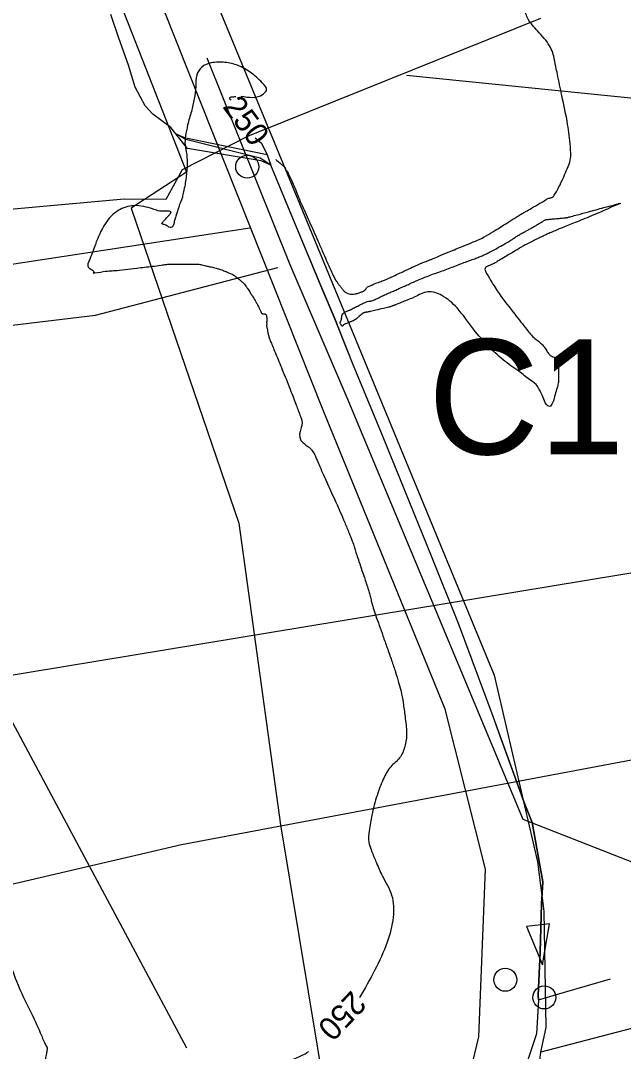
# Model space of a CAD drawing. Extents: x -478232 to -472707, y -1118753 to -1113967.
# Drawn here: x -475969.3 to -475864.4, y -1117320.7 to -1117141.4 of the extents above; entities that cross this region are included whole.
import ezdxf

# ---------------------------------------------------------------- set-up
doc = ezdxf.new("R2010")
doc.units = 0
for name, color, linetype in [('cesty', 7, 'Continuous'), ('el vedeni _VN', 7, 'Continuous'), ('el vedeni_NN', 7, 'Continuous'), ('el vedeni_VVN', 7, 'Continuous'), ('ObPÚ', 7, 'Continuous'), ('plyn_vtl', 7, 'Continuous'), ('silnice', 7, 'Continuous'), ('telekomunikační kabel_O2', 7, 'Continuous'), ('VAK_vodovod', 7, 'Continuous'), ('VAK_vodovod_přípojky', 7, 'Continuous'), ('Vrstevnice_hlavni', 7, 'Continuous'), ('Vrstevnice_popis', 7, 'Continuous')]:
    doc.layers.add(name, color=color, linetype=linetype)

msp = doc.modelspace()

# ---------------------------------------------------------------- linework, layer by layer
at = {"layer": 'cesty'}
msp.add_line((-475877.248, -1117298.53), (-475881.224, -1117298.963), dxfattribs=at)
msp.add_lwpolyline([(-475881.224, -1117298.963), (-475878.485, -1117305.652), (-475877.248, -1117298.53)], dxfattribs=at)
for centre in [(-475929.862, -1117166.808), (-475884.935, -1117308.251), (-475878.155, -1117311.325)]:
    msp.add_circle(centre, 2, dxfattribs=at)
at = {"layer": 'el vedeni _VN'}
msp.add_lwpolyline([(-476054.13, -1117068.87), (-476016.19, -1117179.43), (-476005.061, -1117199.42), (-475940.421, -1117320.088)], dxfattribs=at)
at = {"layer": 'el vedeni_NN'}
for points in [[(-475936.884, -1117147.842), (-475922.455, -1117183.822), (-475912.509, -1117206.959)], [(-476142.527, -1117233.564), (-476143.465, -1117231.005), (-476140.291, -1117228.14), (-476109.493, -1117209.467), (-476071.248, -1117205.717), (-476032.928, -1117201.185), (-475993.047, -1117197.048), (-475956.253, -1117192.65), (-475924.554, -1117184.37)], [(-475912.509, -1117206.959), (-475881.908, -1117280.308), (-475845.463, -1117294.572), (-475796.905, -1117294.234), (-475790.107, -1117303.085)]]:
    msp.add_lwpolyline(points, dxfattribs=at)
at = {"layer": 'el vedeni_VVN'}
for points in [[(-475278.421, -1117142.471), (-475502.649, -1117177.682), (-475743.53, -1117217.796), (-475998.47, -1117259.845), (-476243.025, -1117301.163), (-476469.01, -1117542.153)], [(-476280.708, -1117409.299), (-476225.714, -1117351.077), (-475941.309, -1117284.746), (-475941.309, -1117284.746), (-475650.164, -1117229.984), (-475650.164, -1117229.984), (-475374.719, -1117181.713), (-475324.354, -1117172.684)], [(-476280.708, -1117409.299), (-476225.714, -1117351.077), (-475941.309, -1117284.746), (-475941.309, -1117284.746), (-475650.164, -1117229.984), (-475650.164, -1117229.984), (-475374.719, -1117181.713), (-475324.354, -1117172.684)]]:
    msp.add_lwpolyline(points, dxfattribs=at)
at = {"layer": 'ObPÚ'}
msp.add_lwpolyline([(-475878.82, -1117141.03), (-475927.98, -1117160.79), (-475929.84, -1117161.54), (-475941.17, -1117167.34), (-475944.04, -1117172.5), (-475951.31, -1117172.43), (-476004.5, -1117177.28), (-476018.94, -1117179.19), (-476061.7, -1117183.99), (-476084.27, -1117186.17), (-476089.54, -1117186.61), (-476093.95, -1117187.01), (-476104.79, -1117188.01), (-476125.75, -1117189.99), (-476140.43, -1117190.84), (-476150.96, -1117191.92), (-476159.5, -1117192.77), (-476224.13, -1117203.13), (-476225.41, -1117191.08), (-476226.67, -1117162.34), (-476231.32, -1117146.23), (-476236.27, -1117130.89)], dxfattribs=at)
at = {"layer": 'plyn_vtl'}
msp.add_lwpolyline([(-475595.138, -1117298.191), (-475598.3, -1117295.92), (-475667.47, -1117237.33), (-475686.33, -1117221.12), (-475738.19, -1117171.6), (-475740.56, -1117170), (-475797.11, -1117162.8), (-475845.33, -1117156.66), (-475902.14, -1117150.95)], dxfattribs=at)
at = {"layer": 'silnice'}
for points in [[(-475903.982, -1117378.322), (-475889.519, -1117318.176), (-475888.389, -1117289.008), (-475895.395, -1117261.196), (-475916.638, -1117209.19), (-475969.886, -1117075.455), (-476021.05, -1116948.737), (-476052.923, -1116863.979), (-476081.44, -1116727.192), (-476114.99, -1116491.378), (-476128.411, -1116405.781), (-476137.637, -1116368.017), (-476162.8, -1116322.7), (-476200.543, -1116268.153), (-476239.965, -1116179.199), (-476260.934, -1116109.546), (-476288.613, -1116007.164), (-476289.451, -1115970.24), (-476274.354, -1115930.798), (-476261.922, -1115907.288), (-476366.595, -1115823.727)], [(-476424.073, -1117228.817), (-476282.324, -1117220.425), (-476211.029, -1117212.034), (-476121.67, -1117200.902), (-476029.858, -1117192.732), (-475929.409, -1117177.447)]]:
    msp.add_lwpolyline(points, dxfattribs=at)
at = {"layer": 'telekomunikační kabel_O2'}
for points in [[(-475967.4, -1117098.97), (-475940.43, -1117167.78), (-475950.06, -1117174), (-475931.33, -1117228.82), (-475924.1, -1117281.32), (-475911.23, -1117358.65), (-475927.92, -1117430.83), (-475926.17, -1117443.9), (-475937.75, -1117500.32), (-475940.1, -1117518.94), (-475929.72, -1117521.06), (-475934.27, -1117556.02), (-475935.89, -1117566.02), (-475936.969, -1117573.032)], [(-475950.5, -1117149.33), (-475952.3, -1117144.28), (-475953.59, -1117140.32)], [(-475942.29, -1117161.11), (-475943.19, -1117159.98), (-475946.28, -1117157.66), (-475947.65, -1117156.22), (-475949.35, -1117152.98), (-475950.35, -1117149.74), (-475950.5, -1117149.33)], [(-475925.77, -1117166.55), (-475927.6, -1117165.32), (-475940.53, -1117162.1), (-475942.29, -1117161.11)], [(-475925.77, -1117166.55), (-475927.41, -1117165.77), (-475940.26, -1117163.67), (-475942.29, -1117161.11)], [(-475941.28, -1117161.55), (-475942.29, -1117161.11)], [(-475926.38, -1117164.74), (-475940.58, -1117161.86), (-475941.28, -1117161.55)], [(-475928.5, -1117161.78), (-475927.37, -1117162.72), (-475926.38, -1117164.74)], [(-475926.38, -1117164.74), (-475925.77, -1117166.55)], [(-475912.112, -1117199.556), (-475914.73, -1117193.01), (-475916.77, -1117188.24), (-475925.77, -1117166.55)], [(-475923.355, -1117172.37), (-475916.77, -1117188.24), (-475914.73, -1117193.01), (-475911.57, -1117200.91), (-475906.35, -1117213.5), (-475897.84, -1117234.5), (-475893.13, -1117246.24), (-475887.26, -1117261.95), (-475881.63, -1117277.42), (-475880.27, -1117280.87), (-475878.41, -1117291.19), (-475878.66, -1117295.04), (-475878.84, -1117303.44), (-475879.2, -1117310.91), (-475879.17, -1117311.76)], [(-475879.17, -1117311.76), (-475879.2, -1117310.91), (-475878.84, -1117303.44), (-475878.66, -1117295.04), (-475878.41, -1117291.19), (-475880.27, -1117280.87), (-475881.63, -1117277.42), (-475886.596, -1117263.775)], [(-475879.17, -1117311.76), (-475874.62, -1117310.39), (-475866.596, -1117308.086)], [(-475879.17, -1117311.76), (-475879.52, -1117317.65), (-475882.94, -1117327.87), (-475883.65, -1117331.16), (-475885.38, -1117336.41), (-475888.04, -1117344.37), (-475889.45, -1117349.71), (-475891.45, -1117356.54)]]:
    msp.add_lwpolyline(points, dxfattribs=at)
at = {"layer": 'VAK_vodovod'}
msp.add_lwpolyline([(-475961.022, -1117076.006), (-475947.88, -1117107.78), (-475947.26, -1117108.989), (-475886.863, -1117255.251), (-475879.338, -1117287.714), (-475878.218, -1117296.341), (-475877.862, -1117316.562), (-475878.829, -1117320.819), (-475879.236, -1117324.31), (-475879.403, -1117324.54), (-475921.268, -1117487.378), (-475934.347, -1117574.649), (-475937.667, -1117596.666), (-475938.465, -1117600.746), (-475938.582, -1117601.233), (-475938.757, -1117601.897), (-475940.979, -1117601.583)], dxfattribs=at)
at = {"layer": 'VAK_vodovod_přípojky'}
msp.add_lwpolyline([(-475878.829, -1117320.819), (-475878.667, -1117320.807), (-475780.172, -1117295.12), (-475777.144, -1117294.881), (-475772.889, -1117306.106), (-475760.456, -1117318.245), (-475730.382, -1117337.683), (-475709.998, -1117331.986)], dxfattribs=at)
at = {"layer": 'Vrstevnice_hlavni'}
for points in [[(-475924.869, -1117165.582), (-475924.177, -1117166.164), (-475923.893, -1117166.407), (-475923.671, -1117166.602), (-475923.511, -1117166.749), (-475923.274, -1117167.084), (-475922.96, -1117167.608), (-475922.569, -1117168.319), (-475922.125, -1117169.249), (-475921.627, -1117170.396), (-475921.076, -1117171.761), (-475920.466, -1117173.201), (-475919.798, -1117174.717), (-475919.072, -1117176.307), (-475918.325, -1117177.977), (-475917.556, -1117179.725), (-475916.766, -1117181.553), (-475916.094, -1117183.094), (-475915.54, -1117184.347), (-475915.104, -1117185.312), (-475914.712, -1117186.097), (-475914.365, -1117186.7), (-475914.063, -1117187.123), (-475913.735, -1117187.557), (-475913.38, -1117188.002), (-475913, -1117188.458), (-475912.579, -1117188.775), (-475912.117, -1117188.951), (-475911.613, -1117188.986), (-475911.088, -1117188.941), (-475910.541, -1117188.813), (-475909.972, -1117188.605), (-475909.544, -1117188.384), (-475909.257, -1117188.152), (-475909.111, -1117187.908), (-475908.646, -1117187.607), (-475907.862, -1117187.25), (-475906.759, -1117186.836), (-475905.955, -1117186.527), (-475905.45, -1117186.324), (-475905.244, -1117186.226), (-475904.511, -1117185.883), (-475903.25, -1117185.295), (-475901.462, -1117184.461), (-475900.145, -1117183.861), (-475899.299, -1117183.496), (-475898.924, -1117183.367), (-475898.518, -1117183.211), (-475898.08, -1117183.03), (-475897.611, -1117182.823), (-475896.487, -1117182.352), (-475894.709, -1117181.617), (-475892.277, -1117180.618), (-475890.544, -1117179.904), (-475889.51, -1117179.475), (-475889.176, -1117179.331), (-475888.258, -1117178.808), (-475886.758, -1117177.905), (-475884.675, -1117176.622), (-475883.241, -1117175.734), (-475882.454, -1117175.242), (-475882.317, -1117175.146), (-475882.189, -1117175.064), (-475882.073, -1117174.997), (-475881.967, -1117174.944), (-475881.403, -1117174.622), (-475880.381, -1117174.03), (-475878.901, -1117173.169), (-475877.91, -1117172.594), (-475877.408, -1117172.306), (-475877.395, -1117172.303), (-475877.37, -1117172.3), (-475877.333, -1117172.298), (-475877.284, -1117172.296), (-475877.172, -1117172.269), (-475876.996, -1117172.219), (-475876.756, -1117172.145), (-475876.422, -1117171.763), (-475875.994, -1117171.074), (-475875.471, -1117170.078), (-475874.914, -1117168.901), (-475874.321, -1117167.542), (-475873.694, -1117166.003), (-475873.615, -1117163.305), (-475874.083, -1117159.45), (-475875.099, -1117154.435), (-475875.869, -1117150.689), (-475876.392, -1117148.211), (-475876.669, -1117147.001), (-475877.255, -1117145.76), (-475878.15, -1117144.488), (-475879.354, -1117143.187), (-475880.245, -1117142.157), (-475880.821, -1117141.4), (-475881.084, -1117140.914), (-475881.418, -1117139.944), (-475881.822, -1117138.488)], [(-475930.918, -1117154.529), (-475927.091, -1117154.196), (-475926.503, -1117153.48), (-475927.24, -1117152.214), (-475929.302, -1117150.397), (-475931.471, -1117149.215), (-475933.748, -1117148.667), (-475936.132, -1117148.753), (-475937.769, -1117149.482), (-475938.66, -1117150.856), (-475938.804, -1117152.873), (-475939.115, -1117154.995), (-475939.594, -1117157.22), (-475940.24, -1117159.55), (-475940.601, -1117161.482), (-475940.678, -1117163.016), (-475940.47, -1117164.152), (-475940.352, -1117165.284), (-475940.323, -1117166.413), (-475940.383, -1117167.539), (-475940.507, -1117168.708), (-475940.696, -1117169.92), (-475940.948, -1117171.176), (-475941.162, -1117172.102), (-475941.336, -1117172.697), (-475941.472, -1117172.962), (-475941.64, -1117173.385), (-475941.84, -1117173.966), (-475942.072, -1117174.704), (-475942.295, -1117175.442), (-475942.51, -1117176.178), (-475942.715, -1117176.914), (-475942.981, -1117177.326), (-475943.307, -1117177.413), (-475943.694, -1117177.176), (-475944.026, -1117176.997), (-475944.304, -1117176.874), (-475944.528, -1117176.808), (-475944.67, -1117176.742), (-475944.729, -1117176.675), (-475944.706, -1117176.609), (-475944.521, -1117176.383), (-475944.174, -1117175.997), (-475943.665, -1117175.452), (-475943.322, -1117175.07), (-475943.144, -1117174.851), (-475943.131, -1117174.794), (-475944.198, -1117174.565), (-475946.345, -1117174.163), (-475949.572, -1117173.588), (-475952.308, -1117174.424), (-475954.553, -1117176.67), (-475956.307, -1117180.326), (-475957.293, -1117182.884), (-475957.511, -1117184.344), (-475956.96, -1117184.706), (-475956.631, -1117184.974), (-475956.523, -1117185.148), (-475956.636, -1117185.228), (-475955.435, -1117185.138), (-475952.922, -1117184.878), (-475949.095, -1117184.447), (-475946.401, -1117184.135), (-475944.839, -1117183.942), (-475944.409, -1117183.867), (-475944.026, -1117183.817), (-475943.69, -1117183.791), (-475943.401, -1117183.789), (-475942.688, -1117183.78), (-475941.551, -1117183.761), (-475939.989, -1117183.735), (-475938.839, -1117183.747), (-475938.1, -1117183.797), (-475937.772, -1117183.886), (-475937.265, -1117184.007), (-475936.577, -1117184.16), (-475935.71, -1117184.344), (-475934.887, -1117184.569), (-475934.109, -1117184.835), (-475933.375, -1117185.14), (-475932.838, -1117185.366), (-475932.498, -1117185.513), (-475932.355, -1117185.581), (-475932.074, -1117185.779), (-475931.655, -1117186.106), (-475931.097, -1117186.562), (-475930.689, -1117186.908), (-475930.429, -1117187.143), (-475930.318, -1117187.267), (-475930.097, -1117187.576), (-475929.766, -1117188.071), (-475929.325, -1117188.751), (-475928.979, -1117189.287), (-475928.728, -1117189.677), (-475928.572, -1117189.922), (-475928.361, -1117190.294), (-475928.094, -1117190.794)], [(-475932.653, -1117155.22), (-475932.923, -1117154.883), (-475932.876, -1117154.759), (-475932.647, -1117154.679), (-475931.823, -1117154.607)], [(-475900.706, -1117186.785), (-475899.805, -1117186.392), (-475898.808, -1117185.988), (-475897.717, -1117185.575), (-475896.532, -1117185.153), (-475895.378, -1117184.731), (-475894.256, -1117184.308), (-475893.166, -1117183.885), (-475892.136, -1117183.495), (-475891.165, -1117183.136), (-475890.254, -1117182.81), (-475889.46, -1117182.504), (-475888.782, -1117182.22), (-475888.221, -1117181.958), (-475887.479, -1117181.575), (-475886.556, -1117181.073), (-475885.451, -1117180.451), (-475884.521, -1117179.91), (-475883.768, -1117179.45), (-475883.19, -1117179.071), (-475882.583, -1117178.7), (-475881.946, -1117178.336), (-475881.28, -1117177.98), (-475880.766, -1117177.703), (-475880.403, -1117177.507), (-475880.193, -1117177.39), (-475879.832, -1117177.175), (-475879.321, -1117176.862), (-475878.659, -1117176.449), (-475878.199, -1117176.17), (-475877.94, -1117176.025), (-475877.882, -1117176.013), (-475877.499, -1117175.973), (-475876.792, -1117175.905), (-475875.76, -1117175.809), (-475875.003, -1117175.737), (-475874.521, -1117175.688), (-475874.314, -1117175.663), (-475874.071, -1117175.617), (-475873.793, -1117175.551), (-475873.478, -1117175.465), (-475872.371, -1117175.165), (-475870.469, -1117174.652), (-475867.775, -1117173.924), (-475865.95, -1117173.435), (-475864.996, -1117173.184), (-475864.912, -1117173.172), (-475865.491, -1117173.438), (-475866.735, -1117173.982), (-475868.643, -1117174.805), (-475870.335, -1117175.522), (-475871.814, -1117176.133), (-475873.078, -1117176.639), (-475874.242, -1117177.11), (-475875.308, -1117177.545), (-475876.274, -1117177.946), (-475877.165, -1117178.329), (-475877.982, -1117178.695), (-475878.725, -1117179.044), (-475879.521, -1117179.431), (-475880.372, -1117179.858), (-475881.277, -1117180.323), (-475881.999, -1117180.711), (-475882.54, -1117181.02), (-475882.898, -1117181.252), (-475883.522, -1117181.635), (-475884.411, -1117182.169), (-475885.565, -1117182.855), (-475886.364, -1117183.326), (-475886.808, -1117183.582), (-475886.896, -1117183.624), (-475887.19, -1117183.764), (-475887.691, -1117184.002), (-475888.399, -1117184.338), (-475887.946, -1117185.807), (-475886.332, -1117188.408), (-475883.558, -1117192.141), (-475881.439, -1117194.845), (-475879.975, -1117196.521), (-475879.166, -1117197.167), (-475878.487, -1117197.821), (-475877.938, -1117198.482), (-475877.52, -1117199.151), (-475877.096, -1117199.613), (-475876.667, -1117199.869), (-475875.8, -1117199.969)], [(-475875.8, -1117199.969), (-475875.68, -1117202.403), (-475875.658, -1117203.359), (-475875.673, -1117204.054), (-475875.726, -1117204.488), (-475875.922, -1117205.276), (-475876.259, -1117206.418), (-475876.739, -1117207.915), (-475877.248, -1117208.499), (-475877.786, -1117208.171), (-475878.353, -1117206.931), (-475878.805, -1117205.979), (-475879.141, -1117205.316), (-475879.361, -1117204.941), (-475880.402, -1117204.046), (-475882.264, -1117202.632), (-475884.948, -1117200.698), (-475887.689, -1117198.176), (-475890.488, -1117195.066), (-475893.345, -1117191.367), (-475895.998, -1117189.203), (-475898.449, -1117188.572), (-475900.697, -1117189.475), (-475902.312, -1117190.127), (-475903.293, -1117190.526), (-475903.642, -1117190.674), (-475903.924, -1117190.79), (-475904.137, -1117190.873), (-475904.284, -1117190.925), (-475904.422, -1117190.977), (-475904.554, -1117191.031), (-475904.678, -1117191.085), (-475905.203, -1117191.224), (-475906.13, -1117191.449), (-475907.459, -1117191.76), (-475908.393, -1117191.972), (-475908.932, -1117192.087), (-475909.077, -1117192.105), (-475909.225, -1117192.131), (-475909.377, -1117192.167), (-475909.532, -1117192.212), (-475909.671, -1117192.27), (-475909.793, -1117192.34), (-475909.9, -1117192.424), (-475910.088, -1117192.585), (-475910.358, -1117192.824), (-475910.71, -1117193.139), (-475911.018, -1117193.381), (-475911.281, -1117193.547), (-475911.499, -1117193.639), (-475911.684, -1117193.715), (-475911.836, -1117193.776), (-475911.953, -1117193.823), (-475912.145, -1117193.899), (-475912.41, -1117194.007), (-475912.749, -1117194.146), (-475912.996, -1117194.272), (-475913.15, -1117194.387), (-475913.212, -1117194.49), (-475913.28, -1117194.535), (-475913.355, -1117194.521), (-475913.436, -1117194.45), (-475913.514, -1117194.346), (-475913.588, -1117194.21), (-475913.659, -1117194.043), (-475913.681, -1117193.9), (-475913.654, -1117193.781), (-475913.58, -1117193.687), (-475913.508, -1117193.483), (-475913.439, -1117193.17), (-475913.374, -1117192.747), (-475913.218, -1117192.413), (-475912.972, -1117192.166), (-475912.636, -1117192.007), (-475912.366, -1117191.886), (-475912.161, -1117191.802), (-475912.023, -1117191.756), (-475911.881, -1117191.697), (-475911.735, -1117191.623), (-475911.586, -1117191.536), (-475911.219, -1117191.345), (-475910.634, -1117191.049), (-475909.83, -1117190.648), (-475909.191, -1117190.371), (-475908.716, -1117190.217), (-475908.406, -1117190.187), (-475907.901, -1117190.024), (-475907.201, -1117189.727), (-475906.307, -1117189.297), (-475905.57, -1117188.951), (-475904.991, -1117188.688), (-475904.57, -1117188.508), (-475904.007, -1117188.261), (-475903.302, -1117187.946), (-475902.455, -1117187.563), (-475901.59, -1117187.176), (-475900.706, -1117186.785)], [(-475928.094, -1117190.794), (-475927.771, -1117191.421), (-475927.547, -1117191.876), (-475927.42, -1117192.158), (-475927.392, -1117192.268), (-475927.318, -1117192.345), (-475927.2, -1117192.388), (-475927.036, -1117192.399), (-475926.883, -1117192.418), (-475926.743, -1117192.446), (-475926.615, -1117192.482), (-475926.527, -1117192.705), (-475926.478, -1117193.114), (-475926.469, -1117193.711), (-475926.473, -1117194.117), (-475926.491, -1117194.334), (-475926.521, -1117194.361), (-475926.53, -1117194.407), (-475926.518, -1117194.472), (-475926.483, -1117194.555), (-475926.431, -1117194.79), (-475926.36, -1117195.176), (-475926.272, -1117195.712), (-475926.126, -1117196.282), (-475925.925, -1117196.884), (-475925.666, -1117197.52), (-475925.318, -1117198.365), (-475924.88, -1117199.422), (-475924.352, -1117200.688), (-475923.763, -1117202.127), (-475923.112, -1117203.739), (-475922.399, -1117205.524), (-475921.805, -1117207.037), (-475921.328, -1117208.278), (-475920.97, -1117209.247), (-475920.693, -1117210.011), (-475920.496, -1117210.569), (-475920.379, -1117210.921), (-475920.31, -1117211.202), (-475920.289, -1117211.41), (-475920.315, -1117211.546), (-475920.374, -1117211.801), (-475920.467, -1117212.174), (-475920.594, -1117212.666), (-475920.682, -1117213.023), (-475920.733, -1117213.246), (-475920.746, -1117213.334), (-475920.736, -1117213.492), (-475920.704, -1117213.718), (-475920.649, -1117214.013), (-475920.599, -1117214.235), (-475920.552, -1117214.384), (-475920.51, -1117214.46), (-475920.366, -1117214.609), (-475920.122, -1117214.83), (-475919.777, -1117215.123), (-475919.503, -1117215.343), (-475919.3, -1117215.489), (-475919.169, -1117215.562), (-475918.99, -1117215.724), (-475918.765, -1117215.973), (-475918.494, -1117216.31), (-475918.275, -1117216.627), (-475918.11, -1117216.924), (-475917.998, -1117217.199), (-475917.707, -1117217.875), (-475917.239, -1117218.951), (-475916.592, -1117220.428), (-475915.908, -1117221.958), (-475915.187, -1117223.541), (-475914.428, -1117225.177), (-475913.666, -1117226.891), (-475912.901, -1117228.682), (-475912.132, -1117230.55), (-475911.572, -1117231.97), (-475911.22, -1117232.944), (-475911.078, -1117233.47), (-475910.81, -1117234.327), (-475910.417, -1117235.517), (-475909.897, -1117237.038), (-475909.473, -1117238.279), (-475909.144, -1117239.239), (-475908.911, -1117239.919), (-475908.686, -1117240.672), (-475908.471, -1117241.496), (-475908.263, -1117242.393), (-475907.931, -1117243.542), (-475907.474, -1117244.942), (-475906.892, -1117246.594), (-475906.238, -1117248.44), (-475905.515, -1117250.481), (-475904.72, -1117252.716), (-475904.051, -1117254.726), (-475903.508, -1117256.51), (-475903.092, -1117258.07), (-475902.721, -1117260.055), (-475902.398, -1117262.467)], [(-476090.423, -1117262.79), (-476083.474, -1117249.454), (-476080.106, -1117246.497), (-476076.843, -1117247.249), (-476073.686, -1117251.712), (-476070.615, -1117256.041), (-476067.63, -1117260.234), (-476064.731, -1117264.293), (-476062.606, -1117267.264), (-476061.255, -1117269.149), (-476060.678, -1117269.946), (-476058.499, -1117271.151), (-476054.719, -1117272.763), (-476049.338, -1117274.782), (-476045.003, -1117276.657), (-476041.713, -1117278.387), (-476039.469, -1117279.973), (-476035.812, -1117282.094), (-476030.743, -1117284.749), (-476024.26, -1117287.938), (-476019.593, -1117291.643), (-476016.741, -1117295.864), (-476015.705, -1117300.6), (-476014.893, -1117303.818), (-476014.307, -1117305.517), (-476013.946, -1117305.699), (-476013.413, -1117306.032), (-476012.709, -1117306.516), (-476011.835, -1117307.151), (-476011.205, -1117307.522), (-476010.82, -1117307.628), (-476010.68, -1117307.469), (-476010.532, -1117307.337), (-476010.376, -1117307.23), (-476010.212, -1117307.149), (-476010.007, -1117307.098), (-476009.761, -1117307.076), (-476009.473, -1117307.084), (-476008.834, -1117305.974), (-476007.843, -1117303.746), (-476006.501, -1117300.4), (-476001.994, -1117298.311), (-475994.323, -1117297.479), (-475983.488, -1117297.905), (-475976.137, -1117298.157), (-475972.27, -1117298.236), (-475971.887, -1117298.141), (-475971.562, -1117298.096), (-475971.294, -1117298.099), (-475971.083, -1117298.151), (-475971.138, -1117298.702), (-475971.46, -1117299.752), (-475972.048, -1117301.302), (-475971.575, -1117304.216), (-475970.039, -1117308.495), (-475967.441, -1117314.138), (-475965.687, -1117317.94), (-475964.776, -1117319.9), (-475964.708, -1117320.019), (-475964.722, -1117320.406), (-475964.818, -1117321.061), (-475964.996, -1117321.985), (-475964.878, -1117322.934), (-475964.465, -1117323.909), (-475963.756, -1117324.909), (-475962.45, -1117325.507), (-475960.544, -1117325.703), (-475958.041, -1117325.497), (-475952.863, -1117325.106), (-475945.012, -1117324.53), (-475934.488, -1117323.77), (-475927.002, -1117323.054), (-475922.556, -1117322.382), (-475921.148, -1117321.754), (-475920.173, -1117321.309), (-475919.628, -1117321.047), (-475919.516, -1117320.967), (-475919.421, -1117320.897), (-475919.344, -1117320.835), (-475919.225, -1117320.732)], [(-475902.398, -1117262.467), (-475902.121, -1117265.304), (-475902.44, -1117267.705), (-475903.355, -1117269.67), (-475904.867, -1117271.199), (-475906.172, -1117273.366), (-475907.271, -1117276.171), (-475908.163, -1117279.614), (-475908.632, -1117282.335), (-475908.679, -1117284.333), (-475908.302, -1117285.609), (-475907.517, -1117287.571), (-475906.323, -1117290.218), (-475904.721, -1117293.552), (-475904.45, -1117297.38), (-475905.51, -1117301.704), (-475910.292, -1117311.342)]]:
    msp.add_spline(points, degree=3, dxfattribs=at)

# ---------------------------------------------------------------- texts
at = {"layer": 'cesty'}
msp.add_text('C114a', height=20, rotation=359.99999, dxfattribs=at).set_placement((-475898.368, -1117216.835))
at = {"layer": 'Vrstevnice_popis'}
for rotation, p in [(306.44995, (-475935.162, -1117155.18)), (226.36645, (-475910.674, -1117308.874))]:
    msp.add_text(' 250 ', height=4, rotation=rotation, dxfattribs=at).set_placement(p)

doc.saveas('drawing.dxf')
